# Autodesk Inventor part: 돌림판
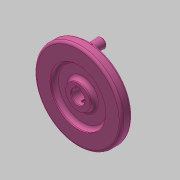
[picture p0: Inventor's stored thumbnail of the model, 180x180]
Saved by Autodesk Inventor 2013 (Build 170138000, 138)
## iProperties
Created: 2019-09
Part Number: 돌림판
Material: 알루미늄 6061
Document SubType Name: Modeling
Designer: mduedu
Density: 2.71 g/cm^3
Mass: 83.7231 g
Surface Area: 107.333 cm^2
Volume: 30.8941 cm^3
Author: mduedu
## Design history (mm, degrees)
sketch "스케치1"
  geometry: L1 (0, 0)-(9, 0); L2 (9, 0)-(9, 36); L3 (9, 36)-(0, 36); L4 (0, 23)-(4, 23); L5 (4, 23)-(4, 10); L6 (4, 10)-(0, 10); L7 (0, 36)-(0, 23); L8 (0, 10)-(0, 0)
  constraints: 16 end point, 4 parallel, 2 horizontal, 2 perpendicular, 1 collinear
  dimensions: "d0" = 72 diameter of L3 L1; "d2" = 9 distance of L2.end L3.end; "d3" = 4 distance between parallel lines of L7 L5; "d4" = 20 diameter of L6 L1; "d5" = 46 diameter of L4 L1
revolve "회전1" sketch "스케치1" stored, may be unused: angle "d6" = 90 deg
fillet "모깎기1" dims "d7" = 3
sketch "스케치2"
  geometry: C1 r 4 at (0, 29); 1 further point
  constraints: 1 centre point, 1 vertical alignment
  dimensions: "d8" = 8 diameter of C1; "d9" = 29 distance of C1.centre point (0, 0)
extrude "돌출1" join sketch "스케치2" distance "d10" = 11; taper "d11" = 0 deg
fillet "모깎기2" dims "d12" = 2
fillet "모깎기3" dims "d13" = 2
chamfer "모따기1" distance "d14" = 1; stored, may be unused: second distance "d15" = 2, angle "d16" = 45 deg
sketch "스케치3"
  geometry: L1 (-2, 5.123)-(2, 5.123); L2 (2, 5.123)-(2, 7.3); L3 (2, 7.3)-(-2, 7.3); L4 (-2, 7.3)-(-2, 5.123); A1 r 5.5 centre (0, 0) between (-2, 5.123) and (2, 5.123); 1 further point
  constraints: 8 end point, 2 parallel, 2 point on circle, 1 centre point, 1 coincident, 1 horizontal, 1 perpendicular
  dimensions: "d17" = 11 diameter of A1; "d18" = 4 distance of L2.end L3.end; "d19" = 12.8 dimension on A1 L3
extrude "돌출2" cut sketch "스케치3" stored distance "d20" = 11; taper "d21" = 0 deg
chamfer "모따기2" distance "d22" = 0.5; stored, may be unused: second distance "d23" = 2, angle "d24" = 45 deg
sketch "스케치4"
  geometry: A1 r 5.5 centre (0, 0) between (-2, 5.123) and (2, 5.123) reference; 2 further points
  constraints: 1 point on circle
hole "구멍1" sketch "스케치4" at (0, -5.5) diameter "d25" = 2.459; stored, may be unused: countersink angle "d29" = 90 deg, drill point angle "d31" = 118 deg; dims "d26" = 6, "d27" = 4, "d28" = 2, "d30" = 5
node "솔리드1"
